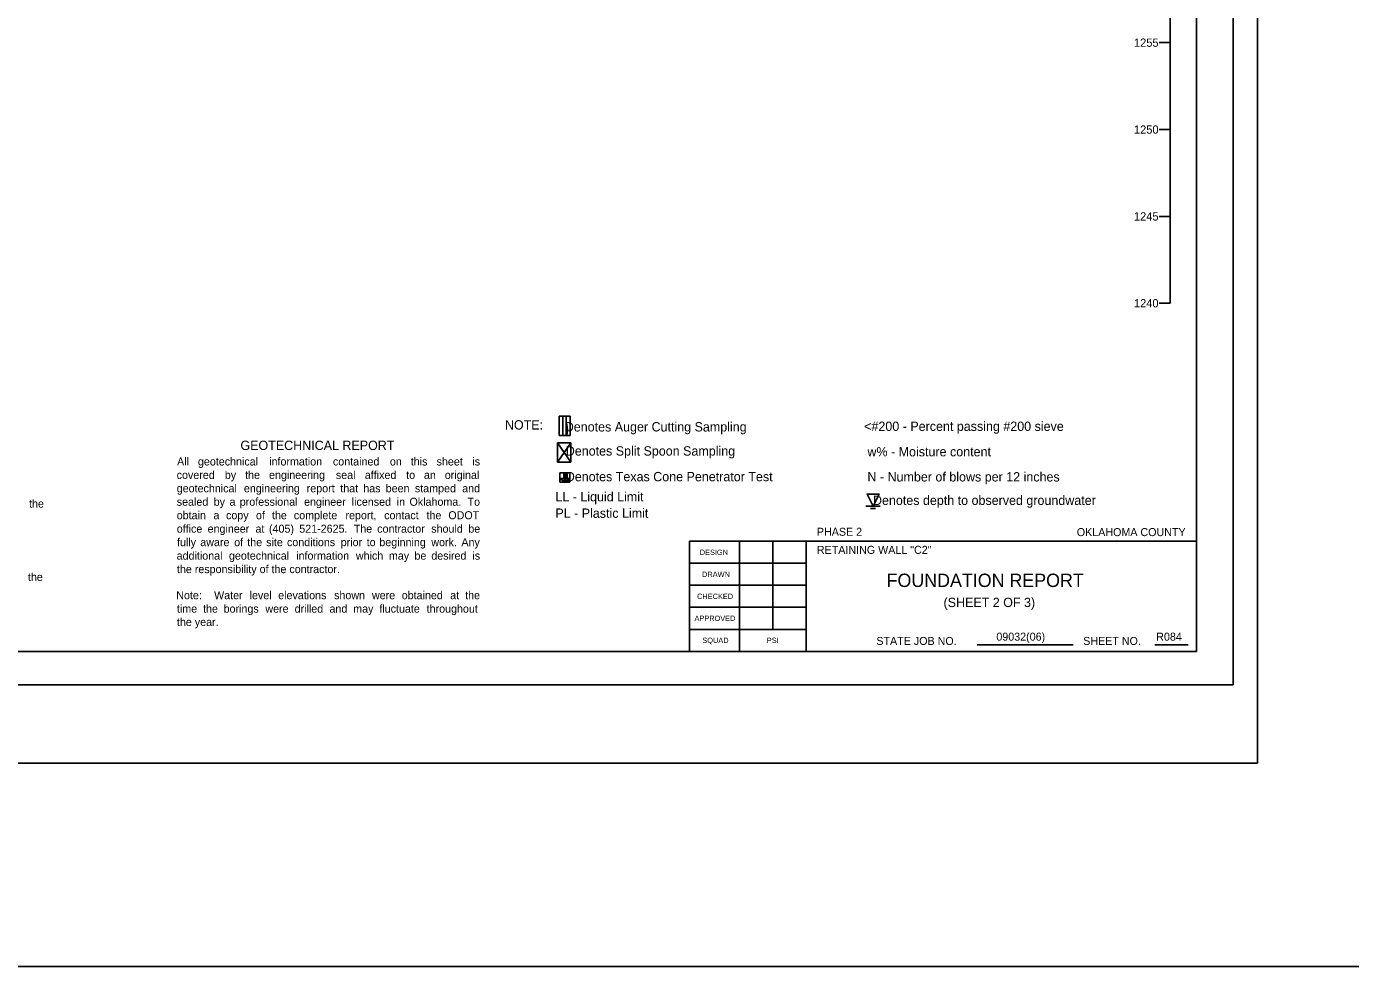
# Model space of a CAD drawing. Extents: x -2 to 138, y 24 to 58.
# Drawn here: x 65.85 to 85.7, y 26.92 to 41.02 of the extents above; entities that cross this region are included whole.
import ezdxf

# ---------------------------------------------------------------- set-up
doc = ezdxf.new("R2010")
doc.units = 0
for name, color, linetype in [('4', 7, 'Continuous'), ('S', 7, 'Continuous'), ('SHT_Plot_Shape_Full', 7, 'Continuous'), ('SHT_Plot_Shape_Half', 7, 'Continuous'), ('SHT_Sheet_Border', 7, 'Continuous'), ('SHT_Standard_Sheet_Lines', 7, 'Continuous'), ('SHT_Standard_Sheet_Txt', 7, 'Continuous'), ('T', 7, 'Continuous'), ('T-5', 7, 'Continuous'), ('Text', 7, 'Continuous')]:
    doc.layers.add(name, color=color, linetype=linetype)

# ---------------------------------------------------------------- blocks, each defined once
blk = doc.blocks.new('DGRFC_WTLEV1_1')
for points in [[(-0.005, 0), (0.005, 0)], [(0, 0), (0.00417, 0.00833), (-0.00417, 0.00833), (0, 0)], [(-0.00167, -0.00167), (0.00167, -0.00167)]]:
    blk.add_lwpolyline(points)

msp = doc.modelspace()

# ---------------------------------------------------------------- linework, layer by layer
for p, q in [((82.996, 36.866), (82.996, 49.887)), ((73.832, 35.172), (73.832, 34.881))]:
    msp.add_line(p, q)
for points in [[(82.996, 40.773), (82.829, 40.773)], [(82.996, 39.47), (82.829, 39.47)], [(82.996, 38.168), (82.829, 38.168)], [(82.996, 36.866), (82.829, 36.866)], [(73.832, 35.172), (73.999, 35.172)], [(73.999, 34.881), (73.999, 35.172)], [(73.832, 34.881), (73.999, 34.881)], [(73.832, 34.881), (73.999, 34.881)]]:
    msp.add_lwpolyline(points)
for points in [[(73.891, 35.172), (73.891, 34.881), (73.941, 34.881), (73.941, 35.172)], [(73.955, 35.005), (73.949, 35.047), (73.941, 35.087), (73.955, 35.005)], [(73.941, 35.087), (73.941, 34.881), (73.955, 35.005), (73.941, 35.087)], [(73.941, 34.881), (73.955, 34.922), (73.955, 35.005), (73.941, 34.881)], [(73.955, 34.922), (73.957, 34.963), (73.955, 35.005), (73.955, 34.922)], [(73.941, 34.881), (73.949, 34.881), (73.955, 34.922), (73.941, 34.881)]]:
    msp.add_lwpolyline(points, close=True)
at = {"layer": 'S'}
msp.add_lwpolyline([(-2.212, 26.92), (137.529, 26.92), (137.529, 58.049), (-2.212, 58.049)], close=True, dxfattribs=at)
at = {"layer": 'SHT_Plot_Shape_Full'}
msp.add_lwpolyline([(48.302, 53.971), (84.302, 53.971), (84.302, 29.971), (48.302, 29.971)], close=True, dxfattribs=at)
at = {"layer": 'SHT_Plot_Shape_Half'}
msp.add_lwpolyline([(49.939, 53.146), (83.939, 53.146), (83.939, 31.146), (49.939, 31.146)], close=True, dxfattribs=at)
at = {"layer": 'SHT_Sheet_Border'}
for p, q in [((75.789, 31.646), (75.789, 33.296)), ((75.789, 33.296), (83.389, 33.296)), ((77.539, 31.646), (77.539, 33.297))]:
    msp.add_line(p, q, dxfattribs=at)
msp.add_lwpolyline([(51.889, 52.646), (83.389, 52.646), (83.389, 31.646), (51.889, 31.646)], close=True, dxfattribs=at)
at = {"layer": 'SHT_Standard_Sheet_Lines'}
for p, q in [((76.539, 31.646), (76.539, 33.297)), ((77.039, 31.976), (77.039, 33.297)), ((80.1, 31.742), (81.54, 31.742)), ((82.765, 31.742), (83.267, 31.742))]:
    msp.add_line(p, q, dxfattribs=at)
for points in [[(77.539, 32.966), (75.789, 32.966)], [(77.539, 32.636), (75.789, 32.636)], [(77.539, 32.306), (75.789, 32.306)], [(77.539, 31.976), (75.789, 31.976)]]:
    msp.add_lwpolyline(points, dxfattribs=at)
at = {"layer": 'Text'}
for p, q in [((73.809, 34.481), (73.809, 34.773)), ((73.845, 34.181), (73.845, 34.322))]:
    msp.add_line(p, q, dxfattribs=at)
for points in [[(73.809, 34.481), (74.009, 34.773)], [(73.809, 34.773), (74.009, 34.481)], [(73.809, 34.773), (74.009, 34.773)], [(74.009, 34.481), (74.009, 34.773)], [(73.809, 34.481), (74.009, 34.481)], [(73.845, 34.322), (73.995, 34.322)], [(73.845, 34.181), (73.995, 34.181)], [(73.995, 34.181), (73.995, 34.322)]]:
    msp.add_lwpolyline(points, dxfattribs=at)
for points in [[(73.905, 34.237), (73.845, 34.237), (73.92, 34.181), (73.905, 34.237)], [(73.905, 34.237), (73.935, 34.322), (73.905, 34.322), (73.905, 34.237)], [(73.905, 34.237), (73.935, 34.237), (73.935, 34.322), (73.905, 34.237)], [(73.905, 34.237), (73.92, 34.181), (73.935, 34.237), (73.905, 34.237)], [(73.92, 34.181), (73.995, 34.237), (73.935, 34.237), (73.92, 34.181)]]:
    msp.add_lwpolyline(points, close=True, dxfattribs=at)

# ---------------------------------------------------------------- block references
at = {"layer": 'Text', "xscale": 21.6, "yscale": 21.6}
msp.add_blockref('DGRFC_WTLEV1_1', (78.54, 33.823), dxfattribs=at)

# ---------------------------------------------------------------- texts
for s, p in [('1255', (82.452, 40.711)), ('1250', (82.452, 39.408)), ('1245', (82.452, 38.106)), ('1240', (82.452, 36.804))]:
    msp.add_text(s, height=0.124).set_placement(p)
at = {"layer": '4'}
msp.add_text('FOUNDATION REPORT', height=0.2, dxfattribs=at).set_placement((78.743, 32.611))
at = {"layer": 'SHT_Standard_Sheet_Txt'}
for s, height, p in [('DESIGN', 0.08, (75.942, 33.091)), ('DRAWN', 0.08, (75.977, 32.761)), ('CHECKED', 0.08, (75.902, 32.431)), ('APPROVED', 0.08, (75.863, 32.101)), ('SQUAD', 0.08, (75.981, 31.771)), ('PSI', 0.08, (76.947, 31.771)), ('STATE JOB NO.', 0.12, (78.59, 31.742)), ('SHEET NO. ', 0.12, (81.691, 31.742))]:
    msp.add_text(s, height=height, dxfattribs=at).set_placement(p)
at = {"layer": 'T'}
for s, p in [('PHASE 2', (77.698, 33.379)), ('OKLAHOMA COUNTY', (81.595, 33.374)), ('RETAINING WALL "C2" ', (77.698, 33.108)), ('09032(06)', (80.389, 31.806)), ('R084', (82.786, 31.806))]:
    msp.add_text(s, height=0.12, dxfattribs=at).set_placement(p)
at = {"layer": 'T-5'}
msp.add_text('(SHEET 2 OF 3)', height=0.14, dxfattribs=at).set_placement((79.597, 32.31))
at = {"layer": 'Text'}
for s, height, p in [('NOTE:', 0.14, (73.021, 34.972)), ('    Denotes Auger Cutting Sampling', 0.14, (73.71, 34.943)), (' <#200 - Percent passing #200 sieve', 0.14, (78.355, 34.951)), ('GEOTECHNICAL REPORT', 0.14, (69.055, 34.665)), ('All', 0.12, (68.105, 34.433)), ('geotechnical', 0.12, (68.418, 34.433)), ('information', 0.12, (69.486, 34.433)), ('contained', 0.12, (70.442, 34.433)), ('this', 0.12, (71.609, 34.433)), ('sheet', 0.12, (71.996, 34.433)), ('is ', 0.12, (72.533, 34.433)), ('    Denotes Split Spoon Sampling', 0.14, (73.725, 34.581)), ('w% - Moisture content', 0.14, (78.456, 34.57)), ('covered', 0.12, (68.099, 34.231)), ('by', 0.12, (68.821, 34.231)), ('the', 0.12, (69.125, 34.231)), ('engineering', 0.12, (69.484, 34.231)), ('seal', 0.12, (70.486, 34.231)), ('affixed', 0.12, (70.92, 34.231)), ('on', 0.12, (71.296, 34.433)), ('to', 0.12, (71.54, 34.231)), ('original ', 0.12, (72.119, 34.231)), ('geotechnical', 0.12, (68.1, 34.031)), ('engineering', 0.12, (69.107, 34.031)), ('that', 0.12, (70.552, 34.031)), ('has', 0.12, (70.897, 34.031)), ('been', 0.12, (71.233, 34.031)), ('stamped', 0.12, (71.671, 34.031)), ('an', 0.12, (71.806, 34.231)), ('and ', 0.12, (72.38, 34.031)), ('    Denotes Texas Cone Penetrator Test', 0.14, (73.725, 34.196)), ('N - Number of blows per 12 inches', 0.14, (78.456, 34.193)), ('sealed', 0.12, (68.1, 33.829)), ('by', 0.12, (68.654, 33.829)), ('professional', 0.12, (69.045, 33.829)), ('engineer', 0.12, (70.009, 33.829)), ('report', 0.12, (70.049, 34.031)), ('licensed', 0.12, (70.724, 33.829)), ('in', 0.12, (71.399, 33.829)), ('Oklahoma.', 0.12, (71.59, 33.829)), ('To ', 0.12, (72.46, 33.829)), (' LL - Liquid Limit', 0.14, (73.725, 33.895)), ('    Denotes depth to observed groundwater', 0.14, (78.331, 33.841)), ('the ', 0.12, (65.886, 33.801)), ('obtain', 0.12, (68.1, 33.627)), ('a', 0.12, (68.892, 33.829)), ('of', 0.12, (69.288, 33.627)), ('the', 0.12, (69.528, 33.627)), ('complete', 0.12, (69.856, 33.627)), ('the', 0.12, (71.845, 33.627)), ('ODOT ', 0.12, (72.172, 33.627)), (' PL - Plastic Limit', 0.14, (73.725, 33.648)), ('office', 0.12, (68.1, 33.425)), ('engineer', 0.12, (68.563, 33.425)), ('a', 0.12, (68.651, 33.627)), ('copy', 0.12, (68.839, 33.627)), ('(405)', 0.12, (69.483, 33.425)), ('report,', 0.12, (70.63, 33.627)), ('The', 0.12, (70.754, 33.425)), ('contact', 0.12, (71.21, 33.627)), ('should', 0.12, (71.916, 33.425)), ('be ', 0.12, (72.472, 33.425)), ('at', 0.12, (69.28, 33.425)), ('521-2625.', 0.12, (69.937, 33.425)), ('contractor', 0.12, (71.106, 33.425)), ('fully', 0.12, (68.104, 33.223)), ('aware', 0.12, (68.453, 33.223)), ('of', 0.12, (68.961, 33.223)), ('the', 0.12, (69.157, 33.223)), ('site', 0.12, (69.441, 33.223)), ('conditions', 0.12, (69.753, 33.223)), ('prior', 0.12, (70.559, 33.223)), ('to', 0.12, (70.948, 33.223)), ('beginning', 0.12, (71.138, 33.223)), ('work.', 0.12, (71.917, 33.223)), ('Any ', 0.12, (72.368, 33.223)), ('additional', 0.12, (68.099, 33.021)), ('geotechnical', 0.12, (68.883, 33.021)), ('information', 0.12, (69.891, 33.021)), ('which', 0.12, (70.786, 33.021)), ('may', 0.12, (71.281, 33.021)), ('be', 0.12, (71.664, 33.021)), ('desired', 0.12, (71.917, 33.021)), ('is ', 0.12, (72.533, 33.021)), ('the ', 0.12, (65.869, 32.701)), ('the responsibility of the contractor.', 0.12, (68.103, 32.819)), ('Note:', 0.12, (68.093, 32.428)), ('Water', 0.12, (68.66, 32.428)), ('level', 0.12, (69.193, 32.428)), ('elevations', 0.12, (69.621, 32.428)), ('shown', 0.12, (70.459, 32.428)), ('were', 0.12, (71.027, 32.428)), ('obtained', 0.12, (71.474, 32.428)), ('at', 0.12, (72.2, 32.428)), ('the ', 0.12, (72.424, 32.428)), ('time', 0.12, (68.103, 32.226)), ('the', 0.12, (68.495, 32.226)), ('borings', 0.12, (68.803, 32.226)), ('were', 0.12, (69.429, 32.226)), ('drilled', 0.12, (69.868, 32.226)), ('and', 0.12, (70.39, 32.226)), ('may', 0.12, (70.746, 32.226)), ('fluctuate', 0.12, (71.138, 32.226)), ('throughout ', 0.12, (71.847, 32.226)), ('the year.', 0.12, (68.103, 32.026))]:
    msp.add_text(s, height=height, dxfattribs=at).set_placement(p)

doc.saveas('drawing.dxf')
